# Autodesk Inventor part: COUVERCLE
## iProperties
Shininess: 64.0
Length Units: 11269
Angle Units: 11279
Time Units: 11290
Mass Units: 11283
Length Display Precision: 3
Angle Display Precision: 2
Compacted: True
Part Number: COUVERCLE
Document SubType Name: Modeling
Created: 2004-07
Material: Par défaut
Designer: Sophie
Density: 1 g/cm^3
Density: 0.0
Volumn: 0.0
Area: 0.0
PropertySet Name: Model Information
Control State: 0
Master: False
Checked Out: False
Author: Sophie
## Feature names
1. Extrusion1
2. Extrusion2
3. Coque2
4. Extrusion4
5. Extrusion5
6. Extrusion6
7. Extrusion7
8. Extrusion8
9. Extrusion9
10. Congé1 [Fillet]
11. Congé2 [Fillet]
12. Extrusion10
13. Extrusion12
14. Extrusion13
15. Extrusion14
16. Symétrie1 [Mirror]
17. Congé3 [Fillet]
18. Congé4 [Fillet]
19. Congé5 [Fillet]
20. Congé6 [Fillet]
21. Congé7 [Fillet]
22. Congé8 [Fillet]
23. Congé9 [Fillet]
24. Congé10 [Fillet]
25. Congé11 [Fillet]
26. Congé12 [Fillet]
27. Congé13 [Fillet]
28. Congé14 [Fillet]
29. Congé15 [Fillet]
30. Congé16 [Fillet]
31. Extrusion15
32. Extrusion16
33. Congé17 [Fillet]
34. Extrusion17
35. Congé18 [Fillet]
36. Congé19 [Fillet]
37. Perçage1 [Hole]
38. Perçage2 [Hole]
39. Perçage3 [Hole]
40. Symétrie2 [Mirror]
41. Congé20 [Fillet]
42. Congé21 [Fillet]
43. Congé22 [Fillet]
44. Congé23 [Fillet]
